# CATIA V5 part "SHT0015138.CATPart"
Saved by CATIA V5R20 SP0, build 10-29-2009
Part number: Part28
Bounding box of the stored display mesh (mm): x 127.726 to 139.273, y -33 to 27, z 17.6 to 27.6
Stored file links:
  E:\张磊\转盘自研\外发冻结数据图纸\2D\2022.11.18-单件图纸\SHT0015138-解锁钣金安装螺栓\SHT0015138.CATPart
  SHT0015138.CATPart
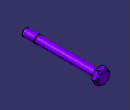
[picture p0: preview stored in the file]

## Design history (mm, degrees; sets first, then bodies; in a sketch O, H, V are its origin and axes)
Body1 (main body)
Body2 "拨片旋转轴"
  Solid1: solid without history
Body3 "改光轴卡环锁紧"
  Solid2: solid without history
